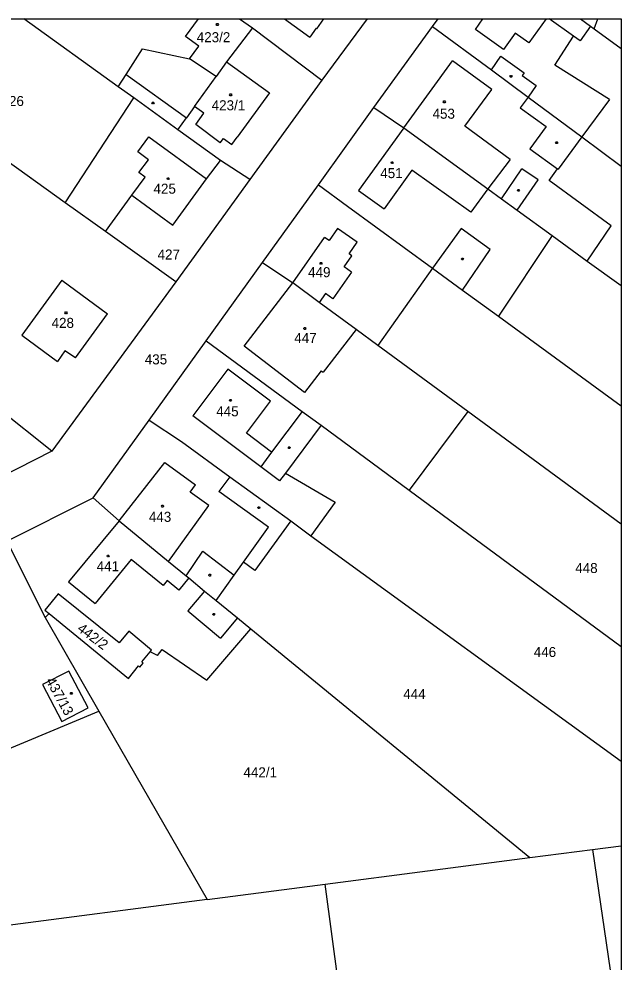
# Model space of a CAD drawing. Extents: x -639621 to -639329, y -1192893 to -1192488.
# Drawn here: x -639431.2 to -639329.3, y -1192647.6 to -1192487.8 of the extents above; entities that cross this region are included whole.
import ezdxf

# ---------------------------------------------------------------- set-up
doc = ezdxf.new("R2010")
doc.units = 0
for name, color, linetype in [('Vrstva 1', 7, 'Continuous'), ('Vrstva 2', 7, 'Continuous'), ('Vrstva 4', 7, 'Continuous'), ('Vrstva 5', 7, 'Continuous'), ('Vrstva 61', 7, 'Continuous')]:
    doc.layers.add(name, color=color, linetype=linetype)

msp = doc.modelspace()

# ---------------------------------------------------------------- linework, layer by layer
at = {"layer": 'Vrstva 1'}
for p, q in [((-639414.41, -1192499.35), (-639430.41, -1192487.83)), ((-639403.02, -1192490.84), (-639400.83, -1192487.83)), ((-639393.87, -1192487.83), (-639391.71, -1192489.38)), ((-639372.29, -1192487.83), (-639379.92, -1192498.19)), ((-639361.21, -1192489.14), (-639360.26, -1192487.83)), ((-639336.13, -1192487.83), (-639334.43, -1192489.07)), ((-639333.81, -1192489.52), (-639333.23, -1192487.83)), ((-639391.71, -1192489.38), (-639396.11, -1192495.13)), ((-639391.71, -1192489.38), (-639379.92, -1192498.19)), ((-639371.16, -1192502.83), (-639361.21, -1192489.14)), ((-639361.21, -1192489.14), (-639351.24, -1192496.49)), ((-639334.43, -1192489.07), (-639336.21, -1192491.56)), ((-639334.43, -1192489.07), (-639333.81, -1192489.52)), ((-639333.81, -1192489.52), (-639329.26, -1192492.88)), ((-639400.8, -1192492.43), (-639403.02, -1192490.84)), ((-639340.48, -1192495.66), (-639337.31, -1192490.77)), ((-639336.21, -1192491.56), (-639337.31, -1192490.77)), ((-639413.09, -1192497.28), (-639410.3, -1192492.89)), ((-639410.3, -1192492.89), (-639402.34, -1192494.6)), ((-639402.34, -1192494.6), (-639400.8, -1192492.43)), ((-639397.86, -1192497.59), (-639402.34, -1192494.6)), ((-639396.11, -1192495.13), (-639397.86, -1192497.59)), ((-639351.24, -1192496.49), (-639345.02, -1192501.08)), ((-639331.24, -1192501.49), (-639340.48, -1192495.66)), ((-639414.41, -1192499.35), (-639413.09, -1192497.28)), ((-639379.92, -1192498.19), (-639392.16, -1192515.05)), ((-639411.8, -1192501.23), (-639414.41, -1192499.35)), ((-639423.39, -1192518.97), (-639411.8, -1192501.23)), ((-639404.31, -1192506.62), (-639411.8, -1192501.23)), ((-639345.02, -1192501.08), (-639335.89, -1192507.81)), ((-639380.52, -1192515.93), (-639371.16, -1192502.83)), ((-639371.16, -1192502.83), (-639366.08, -1192506.31)), ((-639331.24, -1192501.49), (-639335.89, -1192507.81)), ((-639423.39, -1192518.97), (-639443.48, -1192504.61)), ((-639397.1, -1192511.81), (-639404.31, -1192506.62)), ((-639366.08, -1192506.31), (-639351.83, -1192516.65)), ((-639335.89, -1192507.81), (-639339.95, -1192513.32)), ((-639335.89, -1192507.81), (-639329.26, -1192512.76)), ((-639399.45, -1192514.92), (-639397.1, -1192511.81)), ((-639392.16, -1192515.05), (-639397.1, -1192511.81)), ((-639341.47, -1192515.19), (-639340.05, -1192513.25)), ((-639340.05, -1192513.25), (-639339.95, -1192513.32)), ((-639405.18, -1192522.77), (-639399.45, -1192514.92)), ((-639392.16, -1192515.05), (-639404.68, -1192532.35)), ((-639330.96, -1192522.88), (-639341.47, -1192515.19)), ((-639390.01, -1192529.12), (-639380.52, -1192515.93)), ((-639380.52, -1192515.93), (-639375.58, -1192519.55)), ((-639351.83, -1192516.65), (-639349.54, -1192518.31)), ((-639416.56, -1192523.86), (-639423.39, -1192518.97)), ((-639416.56, -1192523.86), (-639412.11, -1192517.69)), ((-639412.11, -1192517.69), (-639405.18, -1192522.77)), ((-639349.54, -1192518.31), (-639346.86, -1192520.25)), ((-639375.58, -1192519.55), (-639361.19, -1192530.05)), ((-639346.86, -1192520.25), (-639340.93, -1192524.55)), ((-639334.99, -1192528.86), (-639330.96, -1192522.88)), ((-639404.68, -1192532.35), (-639416.56, -1192523.86)), ((-639340.93, -1192524.55), (-639350, -1192538.22)), ((-639340.93, -1192524.55), (-639334.99, -1192528.86)), ((-639399.52, -1192542.35), (-639390.01, -1192529.12)), ((-639390.01, -1192529.12), (-639384.88, -1192532.55)), ((-639361.19, -1192530.05), (-639370.46, -1192543.15)), ((-639361.19, -1192530.05), (-639356.11, -1192533.76)), ((-639334.99, -1192528.86), (-639329.26, -1192533.02)), ((-639423.97, -1192532.09), (-639430.76, -1192541.4)), ((-639404.68, -1192532.35), (-639425.67, -1192561.08)), ((-639423.97, -1192532.09), (-639416.25, -1192537.78)), ((-639380.37, -1192535.86), (-639384.88, -1192532.55)), ((-639356.11, -1192533.76), (-639350, -1192538.22)), ((-639374.13, -1192540.45), (-639380.37, -1192535.86)), ((-639421.67, -1192545.27), (-639416.25, -1192537.78)), ((-639350, -1192538.22), (-639329.26, -1192553.36)), ((-639370.46, -1192543.15), (-639374.13, -1192540.45)), ((-639430.76, -1192541.4), (-639424.71, -1192545.89)), ((-639409.19, -1192555.81), (-639399.52, -1192542.35)), ((-639399.52, -1192542.35), (-639383.27, -1192554.32)), ((-639425.67, -1192561.08), (-639447, -1192544.01)), ((-639423.45, -1192544.05), (-639424.71, -1192545.89)), ((-639421.67, -1192545.27), (-639423.45, -1192544.05)), ((-639355.24, -1192554.33), (-639370.46, -1192543.15)), ((-639383.27, -1192554.32), (-639380.06, -1192556.68)), ((-639355.24, -1192554.33), (-639365.14, -1192567.68)), ((-639329.26, -1192573.4), (-639355.24, -1192554.33)), ((-639418.68, -1192568.97), (-639409.19, -1192555.81)), ((-639409.19, -1192555.81), (-639403.73, -1192559.41)), ((-639380.06, -1192556.68), (-639386.12, -1192564.77)), ((-639380.06, -1192556.68), (-639365.14, -1192567.68)), ((-639403.73, -1192559.41), (-639395.53, -1192565.38)), ((-639425.67, -1192561.08), (-639434.43, -1192565.52)), ((-639386.12, -1192564.77), (-639377.7, -1192569.71)), ((-639395.53, -1192565.38), (-639385.22, -1192572.88)), ((-639365.14, -1192567.68), (-639329.26, -1192594.12)), ((-639433.26, -1192576.32), (-639418.68, -1192568.97)), ((-639418.68, -1192568.97), (-639414.27, -1192572.85)), ((-639377.7, -1192569.71), (-639381.78, -1192575.38)), ((-639414.27, -1192572.85), (-639405.9, -1192579.72)), ((-639385.22, -1192572.88), (-639391.28, -1192581.27)), ((-639385.22, -1192572.88), (-639381.78, -1192575.38)), ((-639433.26, -1192576.32), (-639426.82, -1192589.24)), ((-639381.78, -1192575.38), (-639329.26, -1192613.57)), ((-639405.9, -1192579.72), (-639402.9, -1192582.2)), ((-639394.77, -1192582.08), (-639393.2, -1192579.88)), ((-639391.28, -1192581.27), (-639393.2, -1192579.88)), ((-639402.9, -1192582.2), (-639402.48, -1192582.54)), ((-639402.48, -1192582.54), (-639399.79, -1192584.75)), ((-639397.82, -1192586.37), (-639394.77, -1192582.08)), ((-639424.59, -1192585.22), (-639426.83, -1192587.99)), ((-639414.29, -1192593.52), (-639424.59, -1192585.22)), ((-639399.79, -1192584.75), (-639397.82, -1192586.37)), ((-639397.82, -1192586.37), (-639394.23, -1192589.31)), ((-639426.83, -1192587.99), (-639426.11, -1192588.58)), ((-639426.82, -1192589.24), (-639426.11, -1192588.58)), ((-639426.82, -1192589.24), (-639417.68, -1192605.12)), ((-639426.11, -1192588.58), (-639412.71, -1192599.56)), ((-639394.23, -1192589.31), (-639391.98, -1192591.15)), ((-639412.65, -1192591.55), (-639414.29, -1192593.52)), ((-639408.8, -1192594.75), (-639412.65, -1192591.55)), ((-639399.41, -1192599.85), (-639391.98, -1192591.15)), ((-639391.98, -1192591.15), (-639344.75, -1192629.91)), ((-639410.43, -1192596.75), (-639409.04, -1192595.05)), ((-639409.04, -1192595.05), (-639408.8, -1192594.75)), ((-639407.79, -1192595.66), (-639409.04, -1192595.05)), ((-639407.79, -1192595.66), (-639407, -1192594.65)), ((-639407, -1192594.65), (-639399.41, -1192599.85)), ((-639410.74, -1192597.63), (-639410.19, -1192596.95)), ((-639410.19, -1192596.95), (-639410.43, -1192596.75)), ((-639422.78, -1192598.3), (-639427.24, -1192600.6)), ((-639419.54, -1192604.54), (-639422.78, -1192598.3)), ((-639412.71, -1192599.56), (-639410.98, -1192597.44)), ((-639410.98, -1192597.44), (-639410.74, -1192597.63)), ((-639427.24, -1192600.6), (-639424, -1192606.85)), ((-639442.23, -1192615.33), (-639417.68, -1192605.12)), ((-639424, -1192606.85), (-639419.54, -1192604.54)), ((-639417.68, -1192605.12), (-639399.34, -1192636.99)), ((-639344.75, -1192629.91), (-639334.13, -1192628.53)), ((-639334.13, -1192628.53), (-639329.26, -1192627.9)), ((-639334.13, -1192628.53), (-639329.26, -1192661.57)), ((-639379.36, -1192634.4), (-639344.75, -1192629.91)), ((-639399.34, -1192636.99), (-639379.36, -1192634.4)), ((-639374.53, -1192670.58), (-639379.36, -1192634.4)), ((-639399.34, -1192636.99), (-639439.54, -1192642.21))]:
    msp.add_line(p, q, dxfattribs=at)
at = {"layer": 'Vrstva 4'}
for p, q in [((-639386.29, -1192487.83), (-639381.99, -1192490.91)), ((-639380.8, -1192489.51), (-639379.61, -1192487.83)), ((-639353.95, -1192489.62), (-639352.67, -1192487.83)), ((-639341.97, -1192487.83), (-639344.88, -1192491.9)), ((-639337.31, -1192490.77), (-639341.43, -1192487.83)), ((-639380.93, -1192489.42), (-639381.99, -1192490.91)), ((-639380.8, -1192489.51), (-639380.93, -1192489.42)), ((-639349.17, -1192493.03), (-639353.95, -1192489.62)), ((-639347.19, -1192490.25), (-639349.17, -1192493.03)), ((-639344.88, -1192491.9), (-639347.19, -1192490.25)), ((-639366.08, -1192506.31), (-639357.83, -1192494.94)), ((-639351.18, -1192499.82), (-639357.83, -1192494.94)), ((-639351.24, -1192496.49), (-639349.62, -1192494.18)), ((-639349.62, -1192494.18), (-639345.67, -1192496.97)), ((-639396.11, -1192495.13), (-639388.79, -1192500.36)), ((-639413.09, -1192497.28), (-639402.86, -1192504.59)), ((-639401.51, -1192502.7), (-639397.86, -1192497.59)), ((-639345.67, -1192496.97), (-639346, -1192497.44)), ((-639346, -1192497.44), (-639343.63, -1192499.11)), ((-639355.74, -1192506.03), (-639351.18, -1192499.82)), ((-639343.63, -1192499.11), (-639345.02, -1192501.08)), ((-639388.79, -1192500.36), (-639394.27, -1192507.87)), ((-639345.02, -1192501.08), (-639346.34, -1192502.88)), ((-639401.51, -1192502.7), (-639402.86, -1192504.59)), ((-639399.92, -1192503.83), (-639401.51, -1192502.7)), ((-639346.34, -1192502.88), (-639341.98, -1192506.07)), ((-639404.31, -1192506.62), (-639402.86, -1192504.59)), ((-639401.29, -1192505.75), (-639399.92, -1192503.83)), ((-639397.14, -1192508.81), (-639401.29, -1192505.75)), ((-639348.08, -1192511.65), (-639355.74, -1192506.03)), ((-639341.98, -1192506.07), (-639344.73, -1192509.82)), ((-639411.12, -1192510.35), (-639409.22, -1192507.79)), ((-639409.22, -1192507.79), (-639399.45, -1192514.92)), ((-639366.08, -1192506.31), (-639373.76, -1192516.88)), ((-639397.14, -1192508.81), (-639396.6, -1192508.07)), ((-639396.6, -1192508.07), (-639395.18, -1192509.11)), ((-639395.18, -1192509.11), (-639394.27, -1192507.87)), ((-639409.31, -1192511.7), (-639411.12, -1192510.35)), ((-639344.73, -1192509.82), (-639340.05, -1192513.25)), ((-639410.91, -1192513.84), (-639409.31, -1192511.7)), ((-639348.08, -1192511.65), (-639351.83, -1192516.65)), ((-639409.84, -1192514.64), (-639410.91, -1192513.84)), ((-639364.7, -1192513.45), (-639369.37, -1192520.01)), ((-639354.74, -1192520.55), (-639364.7, -1192513.45)), ((-639349.54, -1192518.31), (-639346.06, -1192513.21)), ((-639343.33, -1192515.08), (-639346.06, -1192513.21)), ((-639412.11, -1192517.69), (-639409.84, -1192514.64)), ((-639346.86, -1192520.25), (-639343.33, -1192515.08)), ((-639373.76, -1192516.88), (-639369.37, -1192520.01)), ((-639351.83, -1192516.65), (-639354.74, -1192520.55)), ((-639377.28, -1192523.36), (-639378.71, -1192525.4)), ((-639373.96, -1192525.68), (-639377.28, -1192523.36)), ((-639356.34, -1192523.36), (-639361.19, -1192530.05)), ((-639351.46, -1192526.9), (-639356.34, -1192523.36)), ((-639384.88, -1192532.55), (-639379.49, -1192524.86)), ((-639378.71, -1192525.4), (-639379.49, -1192524.86)), ((-639375.33, -1192527.65), (-639373.96, -1192525.68)), ((-639356.11, -1192533.76), (-639351.46, -1192526.9)), ((-639376.16, -1192529.86), (-639374.85, -1192527.98)), ((-639374.85, -1192527.98), (-639375.33, -1192527.65)), ((-639374.93, -1192530.72), (-639376.16, -1192529.86)), ((-639374.93, -1192530.72), (-639378.1, -1192535.24)), ((-639393.11, -1192543.27), (-639384.88, -1192532.55)), ((-639379.33, -1192534.38), (-639380.37, -1192535.86)), ((-639378.1, -1192535.24), (-639379.33, -1192534.38)), ((-639374.13, -1192540.45), (-639379.7, -1192547.69)), ((-639382.87, -1192551.13), (-639393.11, -1192543.27)), ((-639395.87, -1192547.18), (-639401.79, -1192555.08)), ((-639388.64, -1192552.6), (-639395.87, -1192547.18)), ((-639380.03, -1192547.44), (-639382.87, -1192551.13)), ((-639380.03, -1192547.44), (-639379.7, -1192547.69)), ((-639392.71, -1192558.03), (-639388.64, -1192552.6)), ((-639390.29, -1192563.7), (-639401.79, -1192555.08)), ((-639383.27, -1192554.32), (-639388.44, -1192561.22)), ((-639388.44, -1192561.22), (-639392.71, -1192558.03)), ((-639388.44, -1192561.22), (-639390.29, -1192563.7)), ((-639414.27, -1192572.85), (-639406.54, -1192562.99)), ((-639406.54, -1192562.99), (-639401.32, -1192566.76)), ((-639387.1, -1192566.08), (-639390.29, -1192563.7)), ((-639386.12, -1192564.77), (-639387.1, -1192566.08)), ((-639402.23, -1192568.02), (-639401.32, -1192566.76)), ((-639395.53, -1192565.38), (-639397.36, -1192567.91)), ((-639399.08, -1192570.29), (-639402.23, -1192568.02)), ((-639388.98, -1192573.96), (-639397.36, -1192567.91)), ((-639405.9, -1192579.72), (-639399.08, -1192570.29)), ((-639414.27, -1192572.85), (-639422.82, -1192583.19)), ((-639393.2, -1192579.88), (-639388.98, -1192573.96)), ((-639402.9, -1192582.2), (-639400.07, -1192578.01)), ((-639400.07, -1192578.01), (-639394.77, -1192582.08)), ((-639412.22, -1192579.4), (-639418.35, -1192586.86)), ((-639406.81, -1192583.84), (-639412.22, -1192579.4)), ((-639402.48, -1192582.54), (-639404.16, -1192584.58)), ((-639422.82, -1192583.19), (-639418.35, -1192586.86)), ((-639406.11, -1192582.99), (-639406.81, -1192583.84)), ((-639404.16, -1192584.58), (-639406.11, -1192582.99)), ((-639399.79, -1192584.75), (-639402.62, -1192588.13)), ((-639402.62, -1192588.13), (-639397.1, -1192592.74)), ((-639394.23, -1192589.31), (-639397.1, -1192592.74))]:
    msp.add_line(p, q, dxfattribs=at)
at = {"layer": 'Vrstva 5'}
for points in [[(-639397.55, -1192488.64), (-639397.46, -1192488.79), (-639397.55, -1192488.94), (-639397.73, -1192488.94), (-639397.82, -1192488.79), (-639397.73, -1192488.64)], [(-639347.82, -1192497.42), (-639347.73, -1192497.57), (-639347.82, -1192497.72), (-639348, -1192497.72), (-639348.09, -1192497.57), (-639348, -1192497.42)], [(-639395.3, -1192500.56), (-639395.21, -1192500.71), (-639395.3, -1192500.86), (-639395.48, -1192500.86), (-639395.57, -1192500.71), (-639395.48, -1192500.56)], [(-639408.44, -1192501.93), (-639408.35, -1192502.08), (-639408.44, -1192502.23), (-639408.62, -1192502.23), (-639408.71, -1192502.08), (-639408.62, -1192501.93)], [(-639359.12, -1192501.74), (-639359.03, -1192501.89), (-639359.12, -1192502.04), (-639359.3, -1192502.04), (-639359.39, -1192501.89), (-639359.3, -1192501.74)], [(-639340.08, -1192508.65), (-639339.99, -1192508.8), (-639340.08, -1192508.95), (-639340.26, -1192508.95), (-639340.35, -1192508.8), (-639340.26, -1192508.65)], [(-639367.95, -1192512.03), (-639367.86, -1192512.18), (-639367.95, -1192512.33), (-639368.13, -1192512.33), (-639368.22, -1192512.18), (-639368.13, -1192512.03)], [(-639405.89, -1192514.74), (-639405.8, -1192514.89), (-639405.89, -1192515.04), (-639406.07, -1192515.04), (-639406.16, -1192514.89), (-639406.07, -1192514.74)], [(-639346.56, -1192516.71), (-639346.47, -1192516.86), (-639346.56, -1192517.01), (-639346.74, -1192517.01), (-639346.83, -1192516.86), (-639346.74, -1192516.71)], [(-639356.04, -1192528.37), (-639355.95, -1192528.52), (-639356.04, -1192528.67), (-639356.22, -1192528.67), (-639356.31, -1192528.52), (-639356.22, -1192528.37)], [(-639379.99, -1192529.09), (-639379.9, -1192529.24), (-639379.99, -1192529.39), (-639380.17, -1192529.39), (-639380.26, -1192529.24), (-639380.17, -1192529.09)], [(-639423.18, -1192537.48), (-639423.09, -1192537.63), (-639423.18, -1192537.78), (-639423.36, -1192537.78), (-639423.45, -1192537.63), (-639423.36, -1192537.48)], [(-639382.75, -1192540.13), (-639382.66, -1192540.28), (-639382.75, -1192540.43), (-639382.93, -1192540.43), (-639383.02, -1192540.28), (-639382.93, -1192540.13)], [(-639395.33, -1192552.31), (-639395.24, -1192552.46), (-639395.33, -1192552.61), (-639395.51, -1192552.61), (-639395.6, -1192552.46), (-639395.51, -1192552.31)], [(-639385.37, -1192560.3), (-639385.28, -1192560.45), (-639385.37, -1192560.6), (-639385.55, -1192560.6), (-639385.64, -1192560.45), (-639385.55, -1192560.3)], [(-639406.82, -1192570.23), (-639406.73, -1192570.38), (-639406.82, -1192570.53), (-639407, -1192570.53), (-639407.09, -1192570.38), (-639407, -1192570.23)], [(-639390.52, -1192570.47), (-639390.43, -1192570.62), (-639390.52, -1192570.77), (-639390.7, -1192570.77), (-639390.79, -1192570.62), (-639390.7, -1192570.47)], [(-639416.05, -1192578.66), (-639415.96, -1192578.81), (-639416.05, -1192578.96), (-639416.23, -1192578.96), (-639416.32, -1192578.81), (-639416.23, -1192578.66)], [(-639398.83, -1192581.92), (-639398.74, -1192582.07), (-639398.83, -1192582.22), (-639399.01, -1192582.22), (-639399.1, -1192582.07), (-639399.01, -1192581.92)], [(-639398.15, -1192588.56), (-639398.06, -1192588.71), (-639398.15, -1192588.86), (-639398.33, -1192588.86), (-639398.42, -1192588.71), (-639398.33, -1192588.56)], [(-639422.27, -1192601.91), (-639422.18, -1192602.06), (-639422.27, -1192602.21), (-639422.45, -1192602.21), (-639422.54, -1192602.06), (-639422.45, -1192601.91)]]:
    msp.add_lwpolyline(points, close=True, dxfattribs=at)
at = {"layer": 'Vrstva 61'}
for points in [[(-639621.26, -1192487.83), (-639329.26, -1192487.83)], [(-639329.26, -1192487.83), (-639329.26, -1192893.33)]]:
    msp.add_lwpolyline(points, dxfattribs=at)

# ---------------------------------------------------------------- texts
at = {"layer": 'Vrstva 2'}
for s, p in [('423/2', (-639401.13, -1192491.79)), ('426', (-639434.19, -1192502.6)), ('423/1', (-639398.6, -1192503.32)), ('453', (-639361.2, -1192504.75)), ('451', (-639370.05, -1192514.81)), ('425', (-639408.45, -1192517.45)), ('427', (-639407.76, -1192528.6)), ('449', (-639382.27, -1192531.59)), ('428', (-639425.71, -1192540.18)), ('447', (-639384.6, -1192542.72)), ('435', (-639409.93, -1192546.36)), ('445', (-639397.83, -1192555.16)), ('443', (-639409.23, -1192573.03)), ('441', (-639418.07, -1192581.4)), ('448', (-639337.03, -1192581.7)), ('446', (-639344.06, -1192595.93)), ('444', (-639366.16, -1192603.05)), ('442/1', (-639393.22, -1192616.31))]:
    msp.add_text(s, height=1.7, dxfattribs=at).set_placement(p)
for s, rotation, p in [('442/2', 323.0909, (-639421.5, -1192591.4)), ('437/13', 299.1986, (-639426.76, -1192599.94))]:
    msp.add_text(s, height=1.7, rotation=rotation, dxfattribs=at).set_placement(p)

doc.saveas('drawing.dxf')
